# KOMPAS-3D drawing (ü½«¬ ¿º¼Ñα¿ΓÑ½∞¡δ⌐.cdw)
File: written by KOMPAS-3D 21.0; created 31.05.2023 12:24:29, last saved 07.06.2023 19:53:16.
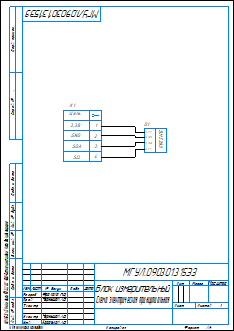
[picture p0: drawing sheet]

Sheet 1: A4, portrait

Document properties: Полное имя файла: C:\Artanis\Учеба\Чертежи\Блок измерительный.cdw

Title block, sheet 1: Наименование: Блок измерительный / Схема электрическая принципиальная; designation: МГУЛ.090301.315ЭЗ; Количество листов документа: 1; Форматы листов документа: A4; stored path: C:\Artanis\Учеба\Чертежи\Основной.cdw; Разработал: Фролова П.В,; Проверил: Чернышов А.В.; Н. контр.: Чернышов А.В.; Утвердил: Корольков А.В.

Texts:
  BME280
  VCC
  GND
  SDA
  SCL
  Цепь
  Стили документа
Dimensions and other numbers on the sheet: 1; 2; 3; 4; 3,3B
